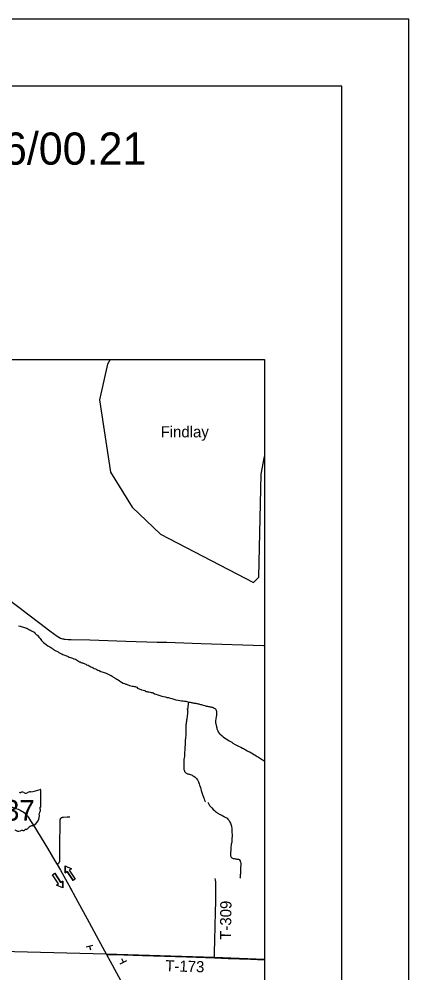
# Model space of a CAD drawing. Extents: x 1 to 1675, y -2 to 1113.
# Drawn here: x 1666.71 to 1675.44, y 1091.69 to 1113.02 of the extents above; entities that cross this region are included whole.
import ezdxf

# ---------------------------------------------------------------- set-up
doc = ezdxf.new("R2010")
doc.units = 0
for name, color, linetype in [('GM_X_Major_Lake_Text', 7, 'Continuous'), ('GM_X_State_Route', 7, 'Continuous'), ('GM_X_State_Shield', 7, 'Continuous'), ('GM_X_Township', 7, 'Continuous'), ('GM_X_Township_Road_Text', 7, 'Continuous'), ('SC_Scratch1', 7, 'Continuous'), ('SH_Border', 7, 'Continuous'), ('SH_Cut_Line', 7, 'Continuous'), ('SH_Data', 7, 'Continuous'), ('SH_Text', 7, 'Continuous'), ('SN_P_Signs', 7, 'Continuous'), ('SN_P_Text', 7, 'Continuous')]:
    doc.layers.add(name, color=color, linetype=linetype)

msp = doc.modelspace()

# ---------------------------------------------------------------- linework, layer by layer
at = {"layer": 'GM_X_State_Route'}
msp.add_lwpolyline([(1665.865, 1095.602), (1665.965, 1095.577), (1666.134, 1095.53), (1666.322, 1095.472), (1666.551, 1095.396), (1666.634, 1095.366), (1666.689, 1095.345), (1666.733, 1095.325), (1666.772, 1095.305), (1666.802, 1095.285), (1666.828, 1095.263), (1666.862, 1095.231), (1666.889, 1095.198), (1666.917, 1095.16), (1666.966, 1095.089), (1667.036, 1094.978), (1667.342, 1094.472), (1667.512, 1094.191), (1667.558, 1094.114), (1667.634, 1093.983), (1667.856, 1093.58), (1667.876, 1093.543)], dxfattribs=at)
at = {"layer": 'GM_X_State_Shield'}
for q in [(1667.193, 1095.774), (1667.193, 1095.406)]:
    msp.add_line((1667.193, 1095.406), q, dxfattribs=at)
for centre, radius, start, end in [((1666.73, 1095.75), 0.0301, 219.7921, 297.1024), ((1666.774, 1095.669), 0.0626, 54.4667, 119.1411), ((1666.855, 1095.78), 0.0753, 233.8562, 294.8282), ((1666.988, 1095.542), 0.198, 97.3462, 120.7689), ((1666.862, 1096.717), 0.984, 275.8445, 288.9065), ((1667.183, 1095.776), 0.0103, 351.8621, 97.738), ((1667.19, 1095.379), 0.016, 107.944, 210.337), ((1667.089, 1095.332), 0.096, 340.033, 23.6496), ((1667.182, 1095.404), 0.0111, 289.6038, 7.7341), ((1666.917, 1095.205), 0.246, 292.3089, 8.9858), ((1667.23, 1095.252), 0.0698, 136.8065, 186.9296), ((1667.021, 1094.843), 0.135, 94.4031, 142.5768), ((1666.7, 1094.996), 0.141, 230.7004, 286.2918), ((1666.781, 1094.753), 0.116, 85.6951, 111.2099), ((1666.791, 1094.943), 0.0752, 268.777, 315.5493), ((1666.859, 1094.875), 0.0212, 65.7517, 132.6484), ((1666.85, 1094.972), 0.0795, 282.8732, 323.2771)]:
    msp.add_arc(centre, radius, start, end, dxfattribs=at)
at = {"layer": 'GM_X_Township'}
msp.add_lwpolyline([(1653.176, 1092.498), (1656.859, 1092.409), (1656.955, 1092.407), (1660.442, 1092.298), (1663.952, 1092.233), (1668.658, 1092.112), (1671.076, 1092.035), (1672.202, 1091.993)], dxfattribs=at)
at = {"layer": 'SC_Scratch1'}
for points in [[(1668.747, 1105.401), (1668.686, 1105.299), (1668.51, 1104.503), (1668.758, 1102.882), (1669.242, 1102.104), (1669.874, 1101.501), (1671.96, 1100.418), (1672.08, 1100.537), (1672.131, 1102.84), (1672.202, 1103.236)], [(1666.695, 1099.451), (1666.735, 1099.44), (1666.778, 1099.428), (1666.807, 1099.42), (1666.826, 1099.412), (1666.85, 1099.403), (1666.866, 1099.398), (1666.88, 1099.392), (1666.896, 1099.384), (1666.92, 1099.373), (1666.944, 1099.359), (1666.965, 1099.348), (1666.986, 1099.335), (1667.016, 1099.321), (1667.042, 1099.304), (1667.071, 1099.277), (1667.101, 1099.25), (1667.119, 1099.239), (1667.138, 1099.215), (1667.151, 1099.198), (1667.167, 1099.18), (1667.18, 1099.163), (1667.196, 1099.144), (1667.212, 1099.123), (1667.228, 1099.104), (1667.241, 1099.087), (1667.257, 1099.074), (1667.284, 1099.055), (1667.315, 1099.03), (1667.355, 1099), (1667.395, 1098.976), (1667.417, 1098.967), (1667.43, 1098.956), (1667.443, 1098.946), (1667.462, 1098.932), (1667.483, 1098.916), (1667.502, 1098.905), (1667.515, 1098.896), (1667.534, 1098.891), (1667.55, 1098.883), (1667.566, 1098.872), (1667.585, 1098.863), (1667.601, 1098.85), (1667.646, 1098.828), (1667.665, 1098.819), (1667.686, 1098.808), (1667.713, 1098.797), (1667.745, 1098.786), (1667.766, 1098.778), (1667.79, 1098.767), (1667.809, 1098.759), (1667.833, 1098.75), (1667.857, 1098.739), (1667.881, 1098.731), (1667.905, 1098.722), (1667.937, 1098.711), (1667.972, 1098.7), (1667.993, 1098.689), (1668.015, 1098.673), (1668.041, 1098.656), (1668.057, 1098.645), (1668.073, 1098.64), (1668.095, 1098.629), (1668.116, 1098.623), (1668.132, 1098.618), (1668.145, 1098.612), (1668.164, 1098.604), (1668.183, 1098.598), (1668.199, 1098.59), (1668.217, 1098.579), (1668.252, 1098.565), (1668.274, 1098.554), (1668.29, 1098.546), (1668.314, 1098.532), (1668.338, 1098.521)], [(1668.338, 1098.521), (1668.364, 1098.508), (1668.391, 1098.496), (1668.418, 1098.483), (1668.447, 1098.469), (1668.474, 1098.458), (1668.503, 1098.449), (1668.541, 1098.428), (1668.591, 1098.413), (1668.613, 1098.405), (1668.639, 1098.394), (1668.661, 1098.386), (1668.688, 1098.372), (1668.717, 1098.361), (1668.749, 1098.347), (1668.77, 1098.339), (1668.792, 1098.325), (1668.81, 1098.311), (1668.872, 1098.268), (1668.898, 1098.254), (1668.928, 1098.24), (1668.957, 1098.218), (1669.002, 1098.188), (1669.042, 1098.169), (1669.072, 1098.155), (1669.096, 1098.147), (1669.114, 1098.141), (1669.128, 1098.133), (1669.146, 1098.128), (1669.162, 1098.122), (1669.184, 1098.116), (1669.208, 1098.108), (1669.237, 1098.102), (1669.262, 1098.099), (1669.283, 1098.094), (1669.304, 1098.088), (1669.326, 1098.08), (1669.344, 1098.074), (1669.363, 1098.055), (1669.448, 1098.014), (1669.521, 1098.002), (1669.534, 1097.994), (1669.555, 1097.983), (1669.574, 1097.98), (1669.588, 1097.974), (1669.614, 1097.969), (1669.641, 1097.966), (1669.663, 1097.96), (1669.687, 1097.957), (1669.711, 1097.946), (1669.74, 1097.93), (1669.772, 1097.916), (1669.815, 1097.902), (1669.86, 1097.888), (1669.903, 1097.874), (1669.943, 1097.865), (1669.984, 1097.857), (1670.016, 1097.848), (1670.053, 1097.842), (1670.088, 1097.831), (1670.128, 1097.82), (1670.171, 1097.806), (1670.222, 1097.795), (1670.267, 1097.786), (1670.31, 1097.777), (1670.348, 1097.774), (1670.38, 1097.769), (1670.409, 1097.763), (1670.444, 1097.76), (1670.484, 1097.751), (1670.511, 1097.743), (1670.541, 1097.74), (1670.559, 1097.734), (1670.576, 1097.731), (1670.592, 1097.728), (1670.61, 1097.725), (1670.629, 1097.722), (1670.648, 1097.719), (1670.667, 1097.717), (1670.68, 1097.714), (1670.693, 1097.711), (1670.715, 1097.705), (1670.734, 1097.702), (1670.752, 1097.697), (1670.771, 1097.691), (1670.79, 1097.685), (1670.811, 1097.682), (1670.867, 1097.663), (1670.897, 1097.655), (1670.924, 1097.649), (1670.948, 1097.646), (1670.964, 1097.643), (1670.977, 1097.637), (1670.999, 1097.634), (1671.02, 1097.632), (1671.042, 1097.629), (1671.058, 1097.623), (1671.076, 1097.609), (1671.09, 1097.601), (1671.105, 1097.588), (1671.116, 1097.574)], [(1670.502, 1097.75), (1670.477, 1097.58), (1670.474, 1097.593), (1670.477, 1097.58), (1670.479, 1097.561), (1670.482, 1097.539), (1670.484, 1097.526), (1670.481, 1097.51), (1670.481, 1097.491), (1670.478, 1097.47), (1670.473, 1097.446), (1670.47, 1097.416), (1670.466, 1097.384), (1670.463, 1097.358), (1670.46, 1097.336), (1670.455, 1097.312), (1670.452, 1097.285), (1670.446, 1097.259), (1670.443, 1097.237), (1670.443, 1097.221), (1670.443, 1097.202), (1670.442, 1097.17), (1670.445, 1097.144), (1670.442, 1097.117), (1670.441, 1097.093), (1670.441, 1097.063), (1670.441, 1097.036), (1670.44, 1097.012), (1670.44, 1096.991), (1670.437, 1096.961), (1670.434, 1096.927), (1670.431, 1096.892), (1670.427, 1096.838), (1670.424, 1096.806), (1670.424, 1096.78), (1670.424, 1096.766), (1670.423, 1096.747), (1670.42, 1096.721), (1670.417, 1096.689), (1670.417, 1096.662), (1670.414, 1096.63), (1670.413, 1096.579), (1670.41, 1096.528), (1670.407, 1096.498), (1670.404, 1096.48), (1670.401, 1096.466), (1670.401, 1096.445), (1670.401, 1096.418), (1670.397, 1096.386), (1670.397, 1096.362), (1670.394, 1096.346), (1670.396, 1096.303), (1670.399, 1096.279), (1670.399, 1096.266), (1670.401, 1096.252), (1670.401, 1096.233), (1670.403, 1096.22), (1670.409, 1096.204), (1670.414, 1096.19), (1670.424, 1096.174), (1670.446, 1096.155), (1670.464, 1096.144), (1670.478, 1096.141), (1670.494, 1096.136), (1670.512, 1096.133), (1670.528, 1096.127), (1670.542, 1096.122), (1670.566, 1096.113), (1670.582, 1096.105), (1670.598, 1096.097), (1670.611, 1096.089), (1670.625, 1096.083), (1670.649, 1096.067), (1670.667, 1096.05), (1670.68, 1096.037), (1670.699, 1096.015), (1670.704, 1096.002), (1670.712, 1095.986), (1670.72, 1095.972), (1670.725, 1095.956), (1670.733, 1095.94), (1670.741, 1095.918), (1670.748, 1095.886), (1670.756, 1095.87), (1670.769, 1095.832), (1670.777, 1095.794), (1670.784, 1095.768), (1670.792, 1095.746), (1670.8, 1095.722), (1670.808, 1095.7), (1670.816, 1095.679), (1670.823, 1095.655), (1670.831, 1095.636), (1670.839, 1095.614), (1670.847, 1095.595), (1670.855, 1095.576), (1670.862, 1095.552), (1670.87, 1095.536), (1670.878, 1095.52), (1670.883, 1095.509), (1670.886, 1095.509)], [(1671.116, 1097.574), (1671.124, 1097.558), (1671.129, 1097.539), (1671.131, 1097.515), (1671.131, 1097.485), (1671.128, 1097.451), (1671.122, 1097.411), (1671.116, 1097.365), (1671.11, 1097.322), (1671.11, 1097.282), (1671.112, 1097.253), (1671.12, 1097.223), (1671.127, 1097.191), (1671.135, 1097.164), (1671.14, 1097.145), (1671.145, 1097.129), (1671.151, 1097.113), (1671.156, 1097.097), (1671.166, 1097.078), (1671.182, 1097.053), (1671.206, 1097.032), (1671.254, 1096.986), (1671.28, 1096.966), (1671.31, 1096.945), (1671.344, 1096.923), (1671.384, 1096.898), (1671.416, 1096.879), (1671.443, 1096.863), (1671.469, 1096.846), (1671.496, 1096.824), (1671.544, 1096.797), (1671.595, 1096.769), (1671.64, 1096.747), (1671.677, 1096.731), (1671.71, 1096.714), (1671.736, 1096.701), (1671.758, 1096.69), (1671.784, 1096.673), (1671.816, 1096.654), (1671.848, 1096.64), (1671.875, 1096.627), (1671.907, 1096.607), (1671.936, 1096.591), (1671.963, 1096.574), (1671.987, 1096.561), (1672.014, 1096.544), (1672.037, 1096.525), (1672.067, 1096.509), (1672.091, 1096.495), (1672.112, 1096.479), (1672.136, 1096.465), (1672.157, 1096.454), (1672.173, 1096.44), (1672.192, 1096.432), (1672.202, 1096.425)], [(1670.935, 1095.504), (1670.957, 1095.46), (1670.963, 1095.446), (1670.976, 1095.427), (1671.003, 1095.401), (1671.027, 1095.374), (1671.056, 1095.344), (1671.086, 1095.32), (1671.11, 1095.299), (1671.128, 1095.282), (1671.144, 1095.269), (1671.16, 1095.258), (1671.176, 1095.248), (1671.192, 1095.237), (1671.208, 1095.229), (1671.227, 1095.221), (1671.251, 1095.21), (1671.27, 1095.199), (1671.289, 1095.188), (1671.307, 1095.18), (1671.326, 1095.172), (1671.339, 1095.164), (1671.353, 1095.156), (1671.366, 1095.145), (1671.385, 1095.126), (1671.395, 1095.113), (1671.411, 1095.092), (1671.422, 1095.075), (1671.43, 1095.057), (1671.441, 1095.035), (1671.449, 1095.014), (1671.459, 1094.992), (1671.465, 1094.971), (1671.47, 1094.909), (1671.473, 1094.885), (1671.472, 1094.859), (1671.475, 1094.84), (1671.475, 1094.816), (1671.478, 1094.792), (1671.478, 1094.765), (1671.478, 1094.733), (1671.475, 1094.701), (1671.475, 1094.666), (1671.472, 1094.637), (1671.469, 1094.61), (1671.466, 1094.586), (1671.461, 1094.564), (1671.456, 1094.532), (1671.453, 1094.508), (1671.45, 1094.487), (1671.45, 1094.465), (1671.447, 1094.444), (1671.447, 1094.425), (1671.447, 1094.409), (1671.445, 1094.39), (1671.442, 1094.372), (1671.442, 1094.353), (1671.442, 1094.34), (1671.442, 1094.318), (1671.444, 1094.305), (1671.45, 1094.291), (1671.46, 1094.273), (1671.471, 1094.259), (1671.49, 1094.249), (1671.506, 1094.243), (1671.525, 1094.243), (1671.546, 1094.238), (1671.57, 1094.235), (1671.583, 1094.232), (1671.597, 1094.232), (1671.61, 1094.229), (1671.624, 1094.227), (1671.64, 1094.221), (1671.656, 1094.192), (1671.661, 1094.178), (1671.666, 1094.165), (1671.672, 1094.144), (1671.674, 1094.125), (1671.674, 1094.106), (1671.674, 1094.085), (1671.669, 1094.053), (1671.669, 1094.026), (1671.666, 1094.002), (1671.666, 1093.975), (1671.663, 1093.951), (1671.663, 1093.924), (1671.663, 1093.9), (1671.66, 1093.879), (1671.66, 1093.86), (1671.66, 1093.841), (1671.657, 1093.828), (1671.657, 1093.812), (1671.655, 1093.807)]]:
    msp.add_lwpolyline(points, dxfattribs=at)
at = {"layer": 'SH_Border'}
msp.add_lwpolyline([(1651.439, 1081.517), (1673.939, 1081.517), (1673.939, 1111.517), (1651.439, 1111.517)], close=True, dxfattribs=at)
at = {"layer": 'SH_Cut_Line'}
msp.add_lwpolyline([(1649.939, 1080.017), (1675.439, 1080.017), (1675.439, 1113.017), (1649.939, 1113.017)], close=True, dxfattribs=at)
at = {"layer": 'SH_Data'}
msp.add_lwpolyline([(1653.176, 1105.401), (1672.202, 1105.401), (1672.202, 1085.801), (1653.176, 1085.801)], close=True, dxfattribs=at)
at = {"layer": 'SH_Text'}
for p, q in [((1667.458, 1093.881), (1667.506, 1093.913)), ((1667.591, 1093.679), (1667.458, 1093.881)), ((1667.64, 1093.711), (1667.506, 1093.913)), ((1667.74, 1094.077), (1667.739, 1093.924)), ((1667.739, 1093.924), (1667.784, 1093.954)), ((1667.74, 1094.077), (1667.88, 1094.017)), ((1667.784, 1093.954), (1667.918, 1093.752)), ((1667.88, 1094.017), (1667.833, 1093.986)), ((1667.833, 1093.986), (1667.966, 1093.784)), ((1667.544, 1093.647), (1667.591, 1093.679)), ((1667.685, 1093.741), (1667.64, 1093.711)), ((1667.685, 1093.588), (1667.685, 1093.741)), ((1667.966, 1093.784), (1667.918, 1093.752)), ((1667.685, 1093.588), (1667.544, 1093.647))]:
    msp.add_line(p, q, dxfattribs=at)
msp.add_lwpolyline([(1667.033, 1094.982), (1667.036, 1094.978), (1667.342, 1094.472), (1667.512, 1094.191), (1667.558, 1094.114), (1667.634, 1093.983), (1667.856, 1093.58), (1667.972, 1093.37), (1668.278, 1092.813), (1668.487, 1092.428), (1668.665, 1092.099), (1668.747, 1091.947), (1669.028, 1091.427), (1669.209, 1091.095), (1669.731, 1090.153)], dxfattribs=at)
for points in [[(1667.506, 1093.913), (1667.64, 1093.711), (1667.685, 1093.741), (1667.685, 1093.588), (1667.544, 1093.647), (1667.591, 1093.679), (1667.458, 1093.881)], [(1667.918, 1093.752), (1667.784, 1093.954), (1667.739, 1093.924), (1667.74, 1094.077), (1667.88, 1094.017), (1667.833, 1093.986), (1667.966, 1093.784)]]:
    msp.add_lwpolyline(points, close=True, dxfattribs=at)
at = {"layer": 'SN_P_Signs'}
for p, q in [((1668.363, 1092.301), (1668.208, 1092.26)), ((1668.286, 1092.281), (1668.306, 1092.204)), ((1668.975, 1091.892), (1669.119, 1091.961)), ((1669.047, 1091.926), (1669.012, 1091.998))]:
    msp.add_line(p, q, dxfattribs=at)
at = {"layer": 'SN_P_Text'}
for points in [[(1665.945, 1100.429), (1666.018, 1100.375), (1666.212, 1100.233), (1666.491, 1100.021), (1666.701, 1099.864), (1666.927, 1099.691), (1667.173, 1099.508), (1667.4, 1099.337), (1667.559, 1099.22), (1667.596, 1099.196), (1667.636, 1099.175), (1667.656, 1099.167), (1667.677, 1099.159), (1667.699, 1099.154), (1667.721, 1099.149), (1667.743, 1099.146), (1667.809, 1099.142), (1667.876, 1099.14)], [(1666.701, 1099.864), (1666.927, 1099.691), (1667.173, 1099.508), (1667.4, 1099.337), (1667.559, 1099.22), (1667.596, 1099.196), (1667.636, 1099.175), (1667.656, 1099.167), (1667.677, 1099.159), (1667.699, 1099.154), (1667.721, 1099.149), (1667.743, 1099.146), (1667.809, 1099.142), (1668.29, 1099.132), (1669.099, 1099.107), (1669.799, 1099.085), (1670.018, 1099.08), (1670.585, 1099.063), (1670.782, 1099.056), (1672.181, 1099.011), (1672.202, 1099.01)], [(1667.558, 1094.114), (1667.578, 1094.127), (1667.589, 1094.135), (1667.594, 1094.139), (1667.601, 1094.146), (1667.604, 1094.149), (1667.608, 1094.156), (1667.611, 1094.161), (1667.614, 1094.167), (1667.616, 1094.173), (1667.617, 1094.181), (1667.619, 1094.191), (1667.619, 1094.204), (1667.619, 1094.219), (1667.621, 1094.269), (1667.621, 1094.294), (1667.621, 1094.387), (1667.623, 1094.544), (1667.623, 1094.666), (1667.625, 1094.911), (1667.628, 1095.086), (1667.628, 1095.099), (1667.629, 1095.104), (1667.63, 1095.112), (1667.631, 1095.118), (1667.633, 1095.126), (1667.635, 1095.131), (1667.637, 1095.137), (1667.642, 1095.144), (1667.648, 1095.15), (1667.653, 1095.154), (1667.658, 1095.158), (1667.665, 1095.161), (1667.673, 1095.164), (1667.681, 1095.166), (1667.691, 1095.168), (1667.703, 1095.169), (1667.782, 1095.173), (1667.843, 1095.175)], [(1667.558, 1094.114), (1667.578, 1094.127), (1667.589, 1094.135), (1667.594, 1094.139), (1667.601, 1094.146), (1667.604, 1094.149), (1667.608, 1094.156), (1667.611, 1094.161), (1667.614, 1094.167), (1667.616, 1094.173), (1667.617, 1094.181), (1667.619, 1094.191), (1667.619, 1094.204), (1667.619, 1094.219), (1667.621, 1094.269), (1667.621, 1094.294), (1667.621, 1094.387), (1667.623, 1094.544), (1667.623, 1094.666), (1667.625, 1094.911), (1667.628, 1095.086), (1667.628, 1095.099), (1667.629, 1095.104), (1667.63, 1095.112), (1667.631, 1095.118), (1667.633, 1095.126), (1667.635, 1095.131), (1667.637, 1095.137), (1667.642, 1095.144), (1667.648, 1095.15), (1667.653, 1095.154), (1667.658, 1095.158), (1667.665, 1095.161), (1667.673, 1095.164), (1667.681, 1095.166), (1667.691, 1095.168), (1667.703, 1095.169), (1667.782, 1095.173), (1667.843, 1095.175)], [(1671.082, 1092.021), (1671.083, 1092.057), (1671.084, 1092.098), (1671.091, 1092.46), (1671.096, 1092.688), (1671.097, 1092.718), (1671.099, 1092.793), (1671.102, 1092.845), (1671.104, 1092.929), (1671.107, 1093.025), (1671.111, 1093.31), (1671.114, 1093.489), (1671.117, 1093.629), (1671.117, 1093.663), (1671.115, 1093.707), (1671.113, 1093.727), (1671.11, 1093.745), (1671.104, 1093.768), (1671.096, 1093.794)], [(1668.665, 1092.099), (1668.847, 1092.096), (1669.472, 1092.077), (1669.965, 1092.058), (1670.455, 1092.042), (1670.886, 1092.027), (1671.082, 1092.021)], [(1671.082, 1092.021), (1671.389, 1092.01), (1671.887, 1091.993), (1672.202, 1091.982)]]:
    msp.add_lwpolyline(points, dxfattribs=at)

# ---------------------------------------------------------------- texts
at = {"layer": 'GM_X_Major_Lake_Text'}
msp.add_text('Findlay', height=0.25, rotation=0.0246, dxfattribs=at).set_placement((1669.879, 1103.662))
at = {"layer": 'GM_X_State_Shield'}
msp.add_text('37', height=0.4641, dxfattribs=at).set_placement((1666.368, 1095.09))
at = {"layer": 'GM_X_Township_Road_Text'}
for s, rotation, p in [('T-309', 89.4372, (1671.456, 1092.426)), ('T-173', 358.3152, (1669.98, 1091.723))]:
    msp.add_text(s, height=0.25, rotation=rotation, dxfattribs=at).set_placement(p)
at = {"layer": 'SH_Border'}
msp.add_text('HAN-SR15/CR180-19.56/00.21', height=0.72, dxfattribs=at).set_placement((1656.125, 1109.761))

doc.saveas('drawing.dxf')
